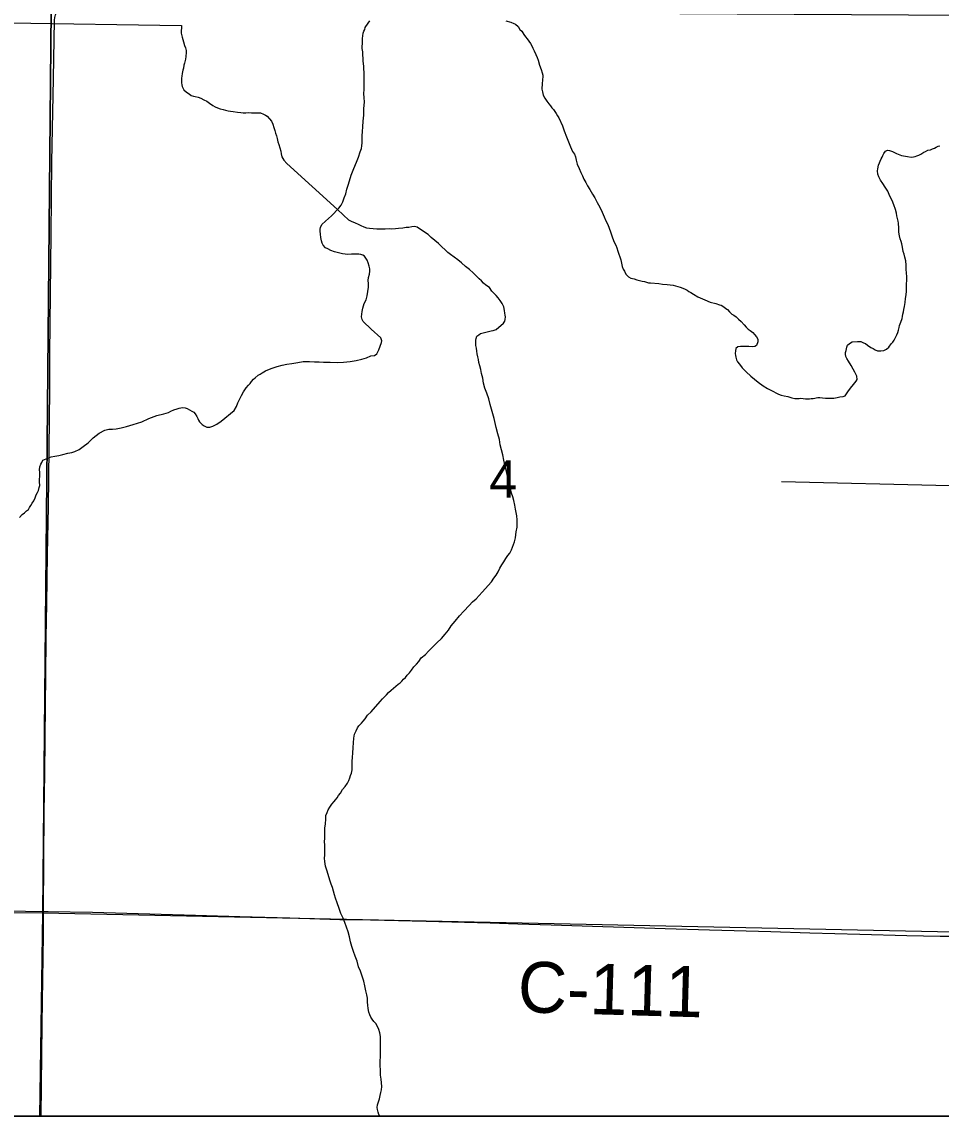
# Model space of a CAD drawing. Extents: x 2.4 to 73.1, y 4.5 to 25.6.
# Drawn here: x 31.406 to 31.92, y 17.985 to 18.597 of the extents above; entities that cross this region are included whole.
import ezdxf

# ---------------------------------------------------------------- set-up
doc = ezdxf.new("R2010")
doc.units = 0
for name, color, linetype in [('GM_X_County_Road', 7, 'Continuous'), ('GM_X_County_Road_Text', 7, 'Continuous'), ('GM_X_Interchange_Ramps', 7, 'Continuous'), ('GM_X_Minor_River', 7, 'Continuous'), ('GM_X_Section', 7, 'Continuous'), ('GM_X_Section_Text', 7, 'Continuous'), ('GM_X_Township_Road', 7, 'Continuous'), ('GM_X_US_Shield', 7, 'Continuous'), ('SH_Cut_Line', 7, 'Continuous'), ('SH_Data', 7, 'Continuous')]:
    doc.layers.add(name, color=color, linetype=linetype)

msp = doc.modelspace()

# ---------------------------------------------------------------- linework, layer by layer
at = {"layer": 'GM_X_County_Road'}
for points in [[(31.41781, 18.09961), (31.4181, 18.12841), (31.41825, 18.15482), (31.41853, 18.17658), (31.41895, 18.21542), (31.4192, 18.23096), (31.41943, 18.25271), (31.41965, 18.27135), (31.42019, 18.29932), (31.42067, 18.32573), (31.42132, 18.39098), (31.42149, 18.41118), (31.42209, 18.478), (31.42258, 18.5184), (31.42337, 18.56502), (31.42402, 18.59767), (31.42419, 18.59923), (31.42458, 18.60073), (31.42487, 18.60136), (31.42554, 18.60207)], [(30.91833, 18.10289), (30.9199, 18.10323), (30.92149, 18.1034), (30.92476, 18.10355), (30.93084, 18.10352), (30.94182, 18.10341), (30.94824, 18.10341), (30.96194, 18.1035), (30.9697, 18.1035), (30.98542, 18.10336), (31.0241, 18.10341), (31.0583, 18.10313), (31.08316, 18.10283), (31.12202, 18.10253), (31.15465, 18.1022), (31.17641, 18.10198), (31.21837, 18.10168), (31.27122, 18.10111), (31.3023, 18.1009), (31.32716, 18.10068), (31.36757, 18.10046), (31.41781, 18.09961)], [(31.41648, 17.98522), (31.41712, 18.03673), (31.41783, 18.08645), (31.41778, 18.09733), (31.41781, 18.09961)], [(31.41781, 18.09961), (31.42041, 18.09955), (31.44528, 18.09913), (31.50276, 18.09756), (31.52762, 18.0968), (31.55559, 18.09599), (31.58354, 18.09518), (31.60063, 18.09491), (31.63171, 18.09418), (31.66745, 18.09315), (31.68298, 18.09265), (31.70162, 18.09213), (31.76532, 18.09009), (31.79017, 18.08933), (31.82435, 18.08833), (31.8461, 18.08757), (31.87406, 18.08684), (31.90047, 18.08612), (31.91896, 18.08575), (31.92122, 18.08572), (31.92813, 18.08576)]]:
    msp.add_lwpolyline(points, dxfattribs=at)
at = {"layer": 'GM_X_Interchange_Ramps'}
msp.add_lwpolyline([(30.40528, 17.98522), (33.45306, 17.98522)], dxfattribs=at)
at = {"layer": 'GM_X_Minor_River'}
for points in [[(30.43533, 18.61131), (31.49498, 18.59472)], [(31.57266, 18.48187), (31.57346, 18.48356), (31.5754, 18.48541), (31.57715, 18.4869), (31.57889, 18.48838), (31.58298, 18.49265), (31.58416, 18.49434), (31.58515, 18.49621), (31.58596, 18.49847), (31.58677, 18.50054), (31.5874, 18.50319), (31.58821, 18.50545), (31.58884, 18.50791), (31.58986, 18.51111), (31.59128, 18.51488), (31.59287, 18.51826), (31.59389, 18.52109), (31.59491, 18.5241), (31.59552, 18.52599), (31.59574, 18.5275), (31.59597, 18.52921), (31.59601, 18.53092), (31.59606, 18.533), (31.59611, 18.53547), (31.59636, 18.53813), (31.59662, 18.54116), (31.59689, 18.54457), (31.59697, 18.54818), (31.59724, 18.55197), (31.5971, 18.55425), (31.59697, 18.55673), (31.59702, 18.559), (31.59708, 18.56147), (31.59714, 18.56413), (31.597, 18.56641), (31.59705, 18.5685), (31.5969, 18.5704), (31.59693, 18.57192), (31.59677, 18.57326), (31.59662, 18.57497), (31.59647, 18.57668), (31.59631, 18.57801), (31.59633, 18.57896), (31.59635, 18.57991), (31.59618, 18.58087), (31.59601, 18.58182), (31.59605, 18.58315), (31.59608, 18.58448), (31.59611, 18.586), (31.59614, 18.58752), (31.59636, 18.58884), (31.59659, 18.59035), (31.59699, 18.59149), (31.5974, 18.59243), (31.59761, 18.59356), (31.59938, 18.59599), (31.60017, 18.5973)], [(31.67621, 18.5973), (31.67904, 18.59648), (31.68074, 18.59587)], [(31.49498, 18.59472), (31.49488, 18.59036), (31.49541, 18.58826), (31.49611, 18.58559), (31.49663, 18.58349), (31.49717, 18.58214), (31.49752, 18.58081), (31.49769, 18.57966), (31.49744, 18.57739), (31.49722, 18.57588), (31.4966, 18.57361), (31.49638, 18.57247), (31.49615, 18.57077), (31.49575, 18.56983), (31.49554, 18.56889), (31.49533, 18.56794), (31.49511, 18.56643), (31.49508, 18.56529), (31.49505, 18.56396), (31.49502, 18.56263), (31.49518, 18.56149), (31.49535, 18.56053), (31.49626, 18.5588), (31.49775, 18.55744), (31.49925, 18.55646), (31.50038, 18.55567), (31.5017, 18.55526), (31.50264, 18.55505), (31.50434, 18.55463), (31.50585, 18.55403), (31.50755, 18.55323), (31.50924, 18.55243), (31.51073, 18.55126), (31.51242, 18.55008), (31.51373, 18.54929), (31.51505, 18.54869), (31.51655, 18.54809), (31.51826, 18.54767), (31.51958, 18.54745), (31.52109, 18.54704), (31.52242, 18.54682), (31.52393, 18.54659), (31.52621, 18.54635), (31.52811, 18.54612), (31.52943, 18.5459), (31.53095, 18.54587), (31.53267, 18.54602), (31.53419, 18.54598), (31.53552, 18.54595), (31.53666, 18.54593), (31.53799, 18.5459), (31.53913, 18.54587), (31.54082, 18.54507), (31.54195, 18.54467), (31.54289, 18.54408), (31.54529, 18.54117), (31.54602, 18.53964), (31.54655, 18.53773), (31.54708, 18.53601), (31.54761, 18.53447), (31.54815, 18.53313), (31.5485, 18.53161), (31.54884, 18.5297), (31.54937, 18.52817), (31.5499, 18.52626), (31.55043, 18.52453), (31.55078, 18.52301), (31.55112, 18.52129), (31.55167, 18.52033), (31.55222, 18.51937), (31.55389, 18.51762), (31.58224, 18.49187)], [(31.68074, 18.59587), (31.68168, 18.59547), (31.68317, 18.59411), (31.68408, 18.59256), (31.6852, 18.59159), (31.68575, 18.59063), (31.6863, 18.58967), (31.68722, 18.58832), (31.68814, 18.58716), (31.68907, 18.586), (31.68999, 18.58465), (31.69072, 18.5833), (31.69145, 18.58195), (31.69218, 18.58061), (31.69308, 18.5785), (31.6938, 18.57677), (31.69434, 18.57524), (31.69504, 18.57257), (31.69593, 18.57008), (31.69665, 18.56816), (31.697, 18.56701), (31.69698, 18.56587), (31.69676, 18.56474), (31.69674, 18.56379), (31.69653, 18.56265), (31.69649, 18.56114), (31.69647, 18.56019), (31.69645, 18.55905), (31.6968, 18.55771), (31.69713, 18.5558), (31.69804, 18.55407), (31.69915, 18.55234), (31.70026, 18.55099), (31.70118, 18.54982), (31.70191, 18.54867), (31.70284, 18.5477), (31.70432, 18.54558), (31.70505, 18.54423), (31.70597, 18.54307), (31.70796, 18.53866), (31.70885, 18.53579), (31.71011, 18.53253), (31.71137, 18.52965), (31.71245, 18.52697), (31.71353, 18.52429), (31.71464, 18.52274), (31.71518, 18.5214), (31.71551, 18.51949), (31.71622, 18.5172), (31.71731, 18.5147), (31.71821, 18.51259), (31.71912, 18.51067), (31.71983, 18.50876), (31.72094, 18.50702), (31.72184, 18.50511), (31.72313, 18.50299), (31.72478, 18.50048), (31.72606, 18.49836), (31.72734, 18.49586), (31.7288, 18.49317), (31.73007, 18.4903), (31.73115, 18.4878), (31.73224, 18.4855), (31.73334, 18.48357), (31.73405, 18.48147), (31.73476, 18.47936), (31.73547, 18.47707), (31.73654, 18.474), (31.73783, 18.47189), (31.73836, 18.47036), (31.73889, 18.46863), (31.73942, 18.46691), (31.73996, 18.46538), (31.74049, 18.46366), (31.74083, 18.46194), (31.74136, 18.46003), (31.7419, 18.4585), (31.74263, 18.45734), (31.74336, 18.45581), (31.74484, 18.45425), (31.74615, 18.45347), (31.74805, 18.45304), (31.74956, 18.45263), (31.75088, 18.45222), (31.75239, 18.45181), (31.75372, 18.45159), (31.75485, 18.45118), (31.75598, 18.45097), (31.75712, 18.45094), (31.76187, 18.45045), (31.76376, 18.45022), (31.76642, 18.44997), (31.76983, 18.44951), (31.77361, 18.44848), (31.77606, 18.44747), (31.77756, 18.44687), (31.7785, 18.44609), (31.77962, 18.4455), (31.78112, 18.44451), (31.78356, 18.44313), (31.78751, 18.44133)], [(31.88269, 18.41336), (31.88402, 18.41295), (31.88497, 18.41293), (31.88592, 18.41291), (31.88744, 18.41306), (31.88898, 18.41379), (31.89033, 18.4149), (31.89171, 18.41676), (31.89249, 18.4177), (31.89327, 18.41882), (31.89427, 18.4207), (31.89486, 18.42182), (31.89527, 18.42314), (31.89568, 18.42446), (31.8961, 18.42597), (31.89631, 18.42711), (31.89671, 18.42805), (31.89711, 18.42899), (31.89773, 18.43088), (31.89794, 18.43201), (31.89816, 18.43333), (31.89857, 18.43465), (31.89879, 18.43598), (31.89902, 18.43768), (31.89945, 18.43995), (31.89969, 18.44223), (31.89993, 18.44412), (31.90016, 18.4462), (31.90022, 18.44867), (31.90026, 18.45038), (31.9003, 18.45228), (31.90035, 18.45437), (31.9002, 18.45627), (31.90006, 18.45855), (31.89992, 18.46084), (31.89978, 18.46312), (31.89926, 18.46522), (31.89892, 18.46694), (31.89838, 18.46847), (31.89805, 18.47075), (31.89753, 18.47266), (31.89718, 18.474), (31.89664, 18.47553), (31.8963, 18.47725), (31.89596, 18.47916), (31.896, 18.48087), (31.89585, 18.48239), (31.89568, 18.48334), (31.8957, 18.48429), (31.89553, 18.48544), (31.89518, 18.48677), (31.89484, 18.4883), (31.89468, 18.48982), (31.89397, 18.49193), (31.89307, 18.49442), (31.89218, 18.49691), (31.89091, 18.49941), (31.88983, 18.50209), (31.88836, 18.5044), (31.88688, 18.50633), (31.88559, 18.50826), (31.88468, 18.51018), (31.88415, 18.51171), (31.884, 18.51343), (31.88421, 18.51456), (31.88464, 18.51664), (31.88605, 18.52022), (31.88664, 18.52115), (31.88704, 18.52209), (31.88745, 18.52322), (31.88843, 18.52453), (31.88958, 18.52508), (31.89072, 18.52486), (31.89242, 18.52425), (31.89467, 18.52325), (31.89731, 18.52205), (31.90071, 18.52141), (31.9028, 18.52117), (31.90414, 18.52133), (31.90509, 18.5215), (31.90605, 18.52186), (31.90701, 18.52222), (31.90816, 18.52276), (31.9099, 18.52386), (31.91085, 18.52422), (31.9122, 18.52495), (31.91354, 18.5253), (31.91469, 18.52584), (31.91584, 18.5262), (31.9168, 18.52674), (31.91796, 18.52729), (31.91876, 18.5275)], [(31.66385, 18.39491), (31.66334, 18.39759), (31.66264, 18.40026), (31.66232, 18.40255), (31.66179, 18.40446), (31.66126, 18.40637), (31.66092, 18.40809), (31.66057, 18.40961), (31.66023, 18.41114), (31.66007, 18.41266), (31.65992, 18.41438), (31.65957, 18.4159), (31.65942, 18.41743), (31.65945, 18.41876), (31.65966, 18.4197), (31.66007, 18.42102), (31.66123, 18.42176), (31.66219, 18.42249), (31.66354, 18.42303), (31.66507, 18.42338), (31.66659, 18.42372), (31.66812, 18.42407), (31.66927, 18.42423), (31.6708, 18.42477), (31.67235, 18.42606), (31.67351, 18.42699), (31.67487, 18.42829), (31.67566, 18.42941), (31.67587, 18.43035), (31.67609, 18.43187), (31.67592, 18.43282), (31.67576, 18.43397), (31.6756, 18.43549), (31.67508, 18.4374), (31.67417, 18.43932), (31.67307, 18.44105), (31.67196, 18.4426), (31.67085, 18.44376), (31.66973, 18.44493), (31.66843, 18.44629), (31.66715, 18.44821), (31.66508, 18.44959), (31.66378, 18.45076), (31.66267, 18.45192), (31.66136, 18.45309), (31.65988, 18.45465), (31.65801, 18.4564), (31.65597, 18.45834), (31.65373, 18.4601), (31.65149, 18.46205), (31.64944, 18.46381), (31.64738, 18.46518), (31.64532, 18.46675), (31.64383, 18.46792), (31.64234, 18.46928), (31.64047, 18.47104), (31.63861, 18.47279), (31.63656, 18.47454), (31.63451, 18.4763), (31.63283, 18.47786), (31.62796, 18.481), (31.62665, 18.48198), (31.62533, 18.48239), (31.62381, 18.48224), (31.62209, 18.4819), (31.62057, 18.48174), (31.61866, 18.4814), (31.61637, 18.48127), (31.61466, 18.48111), (31.61256, 18.48097), (31.61104, 18.481), (31.60876, 18.48087), (31.60648, 18.48092), (31.6042, 18.48097), (31.60211, 18.48102), (31.60002, 18.48125), (31.59851, 18.48148), (31.597, 18.48208), (31.59549, 18.48268), (31.59399, 18.48348), (31.5923, 18.48428), (31.59003, 18.48509), (31.58853, 18.48588), (31.58223, 18.49186)], [(31.5019, 18.37861), (31.50264, 18.37765), (31.50356, 18.37611), (31.5041, 18.37515), (31.50446, 18.37419), (31.50501, 18.37323), (31.5065, 18.37167), (31.50762, 18.37089), (31.50913, 18.37028), (31.51084, 18.37025), (31.51256, 18.37078), (31.51468, 18.37187), (31.51719, 18.37352), (31.52436, 18.37963), (31.52573, 18.38169), (31.52654, 18.38376), (31.52754, 18.38601), (31.52853, 18.38789), (31.52972, 18.38995), (31.5311, 18.3922), (31.53247, 18.39369), (31.53344, 18.39462), (31.53403, 18.39575), (31.53521, 18.39705), (31.53617, 18.39779), (31.53792, 18.39927), (31.53888, 18.39981), (31.54004, 18.40055), (31.54196, 18.40165), (31.54504, 18.4031), (31.54848, 18.40416), (31.55135, 18.40485), (31.55383, 18.40537), (31.55669, 18.40587), (31.55994, 18.40637), (31.56299, 18.40687), (31.5666, 18.40698), (31.56926, 18.40673), (31.57192, 18.40667), (31.57439, 18.40661), (31.578, 18.40653), (31.58199, 18.40644), (31.5856, 18.40655), (31.58922, 18.40685), (31.59266, 18.40753), (31.59572, 18.40822), (31.59839, 18.40892), (31.60089, 18.41001), (31.6028, 18.41034), (31.60415, 18.41126), (31.60534, 18.41352), (31.60596, 18.41559), (31.60676, 18.41747), (31.60697, 18.41842), (31.60644, 18.42014), (31.60458, 18.42189), (31.6029, 18.42326), (31.60104, 18.42501), (31.59657, 18.42929), (31.59603, 18.43044), (31.59568, 18.43197), (31.59571, 18.43329), (31.59594, 18.43481), (31.59636, 18.4367), (31.59718, 18.43934), (31.59818, 18.44141), (31.5988, 18.44367), (31.59923, 18.44613), (31.59947, 18.44841), (31.59952, 18.45049), (31.59937, 18.45221), (31.5996, 18.45391), (31.60002, 18.4558), (31.60025, 18.4575), (31.60027, 18.45864), (31.59993, 18.46017), (31.5994, 18.46208), (31.59868, 18.46362), (31.59794, 18.46477), (31.5972, 18.46574), (31.59626, 18.46633), (31.59532, 18.46673), (31.59419, 18.46695), (31.5921, 18.467), (31.59, 18.46685), (31.58791, 18.46671), (31.58639, 18.46693), (31.58507, 18.46715), (31.5828, 18.46759), (31.58053, 18.46821), (31.57846, 18.46901), (31.57676, 18.46981), (31.57545, 18.47041), (31.57415, 18.47196), (31.57361, 18.47311), (31.57326, 18.47445), (31.57291, 18.47616), (31.57277, 18.47807), (31.57243, 18.47978), (31.57245, 18.48092), (31.57266, 18.48187)], [(31.78751, 18.44133), (31.79053, 18.44012), (31.79355, 18.43929), (31.79563, 18.43868), (31.79657, 18.43847), (31.79807, 18.43748), (31.79919, 18.43651), (31.80013, 18.43592), (31.80124, 18.43475), (31.80254, 18.43339), (31.80367, 18.4328), (31.80498, 18.43182), (31.80628, 18.43065), (31.80777, 18.42929), (31.80944, 18.42735), (31.81055, 18.42619), (31.81167, 18.42502), (31.81279, 18.42424), (31.81429, 18.42306), (31.81522, 18.42209), (31.81633, 18.42074), (31.81706, 18.41939), (31.81702, 18.41787), (31.81641, 18.4158), (31.81544, 18.41525), (31.81411, 18.41509), (31.81202, 18.41533), (31.80974, 18.41538), (31.80746, 18.41524), (31.80593, 18.41508), (31.80477, 18.41416), (31.80455, 18.41284), (31.80452, 18.41132), (31.80469, 18.41036), (31.80485, 18.40941), (31.8052, 18.40788), (31.80575, 18.40673), (31.80686, 18.40538), (31.80833, 18.40344), (31.81056, 18.40111), (31.81317, 18.39878), (31.81728, 18.39545), (31.82008, 18.3933), (31.82252, 18.39192), (31.8244, 18.39093), (31.8259, 18.39013), (31.82722, 18.38934), (31.82872, 18.38874), (31.83023, 18.38814), (31.83174, 18.38772), (31.83382, 18.3873), (31.83609, 18.38668), (31.83779, 18.38626), (31.83893, 18.38623), (31.84026, 18.3862), (31.84122, 18.38637), (31.84236, 18.38634), (31.84368, 18.38613), (31.84501, 18.38609), (31.84596, 18.38607), (31.84692, 18.38624), (31.84806, 18.38622), (31.85073, 18.38673), (31.85168, 18.38689), (31.8532, 18.38667), (31.8549, 18.38644), (31.85604, 18.38642), (31.85757, 18.38638), (31.85966, 18.38653), (31.86138, 18.38687), (31.86291, 18.38721), (31.86481, 18.38736), (31.86596, 18.38771), (31.86734, 18.38996), (31.86891, 18.39202), (31.87066, 18.39407), (31.87204, 18.39593), (31.87263, 18.39687), (31.87248, 18.39877), (31.87139, 18.40089), (31.87048, 18.40262), (31.86919, 18.40473), (31.86772, 18.40705), (31.86681, 18.40859), (31.86626, 18.40974), (31.8661, 18.41107), (31.86613, 18.41202), (31.86653, 18.41315), (31.86676, 18.41486), (31.86717, 18.41599), (31.86833, 18.41691), (31.86987, 18.41783), (31.87273, 18.41814), (31.87368, 18.41812), (31.87463, 18.4181), (31.87613, 18.4173), (31.87726, 18.4169), (31.87838, 18.41611), (31.88025, 18.41474), (31.88157, 18.41414), (31.88269, 18.41336)], [(31.58912, 18.17418), (31.58953, 18.1755), (31.58994, 18.17682), (31.59037, 18.17871), (31.59042, 18.18099), (31.59047, 18.18345), (31.59052, 18.18573), (31.59076, 18.18801), (31.59103, 18.19123), (31.59109, 18.19389), (31.59133, 18.19635), (31.59176, 18.19862), (31.59257, 18.2005), (31.59336, 18.20219), (31.59415, 18.20331), (31.59551, 18.2048), (31.59649, 18.20592), (31.59766, 18.20722), (31.59904, 18.20928), (31.60098, 18.21114), (31.60605, 18.21691), (31.60742, 18.2184), (31.60859, 18.2197), (31.60956, 18.22063), (31.61073, 18.22194), (31.61209, 18.22323), (31.61344, 18.22434), (31.6148, 18.22545), (31.61615, 18.22656), (31.61712, 18.2273), (31.61809, 18.22823), (31.61907, 18.22935), (31.62023, 18.23027), (31.62121, 18.23158), (31.62238, 18.23288), (31.62355, 18.23437), (31.62493, 18.23624), (31.62629, 18.23773), (31.62765, 18.23922), (31.62903, 18.24128), (31.63135, 18.24313), (31.63311, 18.24499), (31.63525, 18.24722), (31.63777, 18.24963), (31.6403, 18.25204), (31.64244, 18.25446), (31.64421, 18.2567), (31.64578, 18.25914), (31.64793, 18.26175), (31.65028, 18.26473), (31.65281, 18.26734), (31.65573, 18.2705), (31.65768, 18.27254), (31.65962, 18.27421), (31.66137, 18.27607), (31.66312, 18.27793), (31.66488, 18.27998), (31.66644, 18.28184), (31.6682, 18.28389), (31.66957, 18.28576), (31.67094, 18.28744), (31.67193, 18.28932), (31.67293, 18.29138), (31.67411, 18.29326), (31.6751, 18.29494), (31.67628, 18.29682), (31.67746, 18.2985), (31.67844, 18.29981), (31.67944, 18.30168), (31.68106, 18.30621), (31.68168, 18.30847), (31.68213, 18.31169), (31.68257, 18.31434), (31.68262, 18.31643), (31.68267, 18.31852), (31.68233, 18.32061), (31.682, 18.32252), (31.68166, 18.32443), (31.68133, 18.32671), (31.68082, 18.3292), (31.6801, 18.3313), (31.67939, 18.33341), (31.6787, 18.33665), (31.67781, 18.33933), (31.67731, 18.34219), (31.67662, 18.34543), (31.67593, 18.34849), (31.67524, 18.35173), (31.67455, 18.35479), (31.67385, 18.35765), (31.67315, 18.36033), (31.67265, 18.36338), (31.67177, 18.36644), (31.6709, 18.37006), (31.66968, 18.37503), (31.66863, 18.37904), (31.66758, 18.38287), (31.6667, 18.38611), (31.66563, 18.38918), (31.66455, 18.39205), (31.66385, 18.39491)], [(31.40439, 18.31984), (31.40595, 18.32151), (31.4073, 18.32243), (31.40846, 18.32354), (31.40943, 18.32428), (31.41003, 18.32541), (31.41081, 18.32653), (31.4116, 18.32784), (31.41239, 18.32915), (31.41319, 18.33066), (31.4138, 18.33235), (31.41459, 18.33366), (31.41499, 18.33479), (31.41541, 18.33649), (31.41582, 18.33762), (31.41567, 18.33972), (31.41571, 18.34143), (31.41574, 18.34256), (31.41576, 18.34351), (31.41579, 18.34503), (31.41563, 18.34637), (31.41586, 18.34807), (31.41646, 18.34958), (31.41687, 18.35052), (31.41747, 18.35183), (31.42207, 18.35363), (31.42417, 18.35396), (31.42646, 18.35448), (31.42875, 18.355), (31.43143, 18.3557), (31.43372, 18.35603), (31.43544, 18.35656), (31.43775, 18.35783), (31.44007, 18.35949), (31.44278, 18.36152), (31.44569, 18.3643), (31.44898, 18.36689), (31.45206, 18.36853), (31.45435, 18.36905), (31.45645, 18.36919), (31.45854, 18.36933), (31.46121, 18.36984), (31.46427, 18.37053), (31.46791, 18.37178), (31.47289, 18.37319), (31.47673, 18.375), (31.48114, 18.3768), (31.48515, 18.37766), (31.48764, 18.37836), (31.48899, 18.37909), (31.49072, 18.38), (31.49263, 18.38053), (31.49378, 18.38089), (31.4955, 18.38123), (31.49701, 18.381), (31.49815, 18.3806), (31.49946, 18.38), (31.50078, 18.37921), (31.5019, 18.37861)], [(31.60583, 17.98522), (31.60524, 17.98616), (31.60489, 17.98749), (31.60454, 17.98883), (31.60437, 17.98997), (31.6046, 17.99149), (31.60501, 17.99319), (31.60562, 17.99488), (31.60605, 17.99677), (31.60646, 17.99847), (31.60669, 17.99999), (31.60692, 18.00169), (31.60663, 18.00588), (31.6063, 18.00816), (31.60617, 18.01083), (31.60604, 18.01349), (31.6061, 18.01615), (31.60615, 18.01842), (31.6062, 18.0207), (31.60625, 18.02298), (31.60631, 18.02564), (31.60617, 18.02773), (31.60621, 18.02963), (31.60588, 18.03173), (31.60535, 18.03364), (31.60463, 18.03536), (31.60353, 18.03691), (31.60241, 18.03807), (31.60149, 18.03942), (31.60076, 18.04058), (31.60021, 18.04173), (31.59968, 18.04326), (31.59934, 18.04536), (31.5992, 18.04726), (31.59904, 18.04897), (31.5989, 18.05107), (31.59856, 18.05297), (31.59805, 18.05527), (31.59753, 18.05794), (31.59683, 18.06061), (31.59595, 18.06348), (31.59506, 18.06616), (31.59397, 18.06865), (31.5931, 18.0719), (31.59202, 18.07458), (31.59113, 18.07726), (31.59024, 18.07994), (31.58953, 18.08262), (31.58884, 18.08548), (31.58814, 18.08816), (31.58725, 18.09084), (31.58635, 18.09333), (31.58527, 18.09582), (31.584, 18.09851), (31.58311, 18.10119), (31.58204, 18.10444), (31.58115, 18.10693), (31.58043, 18.10884), (31.57991, 18.11095), (31.57938, 18.11305), (31.57866, 18.11477), (31.57813, 18.11649), (31.57618, 18.12262), (31.57547, 18.12491), (31.57515, 18.12758), (31.575, 18.12929), (31.57503, 18.131), (31.57507, 18.13271), (31.57512, 18.13461), (31.57516, 18.13669), (31.57501, 18.1386), (31.57505, 18.1403), (31.5751, 18.1422), (31.57514, 18.1441), (31.57519, 18.14638), (31.57543, 18.14846), (31.57568, 18.15131), (31.57572, 18.1532), (31.57633, 18.1549), (31.57694, 18.15641), (31.57792, 18.1579), (31.5791, 18.15959), (31.58027, 18.16108), (31.58105, 18.16201), (31.58203, 18.16313), (31.58282, 18.16444), (31.5838, 18.16575), (31.58499, 18.16781), (31.58655, 18.16949), (31.58773, 18.17136), (31.58852, 18.17286), (31.58912, 18.17418)]]:
    msp.add_lwpolyline(points, dxfattribs=at)
at = {"layer": 'GM_X_Section'}
for points in [[(30.9167, 18.60894), (30.95137, 18.60852), (31.42217, 18.60344), (31.41744, 18.09871), (30.91045, 18.10349)], [(31.42217, 18.60344), (31.45381, 18.60328), (31.93338, 18.60046), (31.92638, 18.08802), (31.41744, 18.09871)]]:
    msp.add_lwpolyline(points, close=True, dxfattribs=at)
at = {"layer": 'GM_X_Township_Road'}
msp.add_lwpolyline([(31.83037, 18.33979), (31.92435, 18.33759), (31.93148, 18.33749)], dxfattribs=at)
at = {"layer": 'GM_X_US_Shield'}
for points in [[(30.90891, 17.98522), (31.41579, 17.98522), (31.41744, 18.09871), (30.91045, 18.10349)], [(31.41579, 17.98522), (31.92492, 17.98522), (31.92638, 18.08802), (31.41744, 18.09871)]]:
    msp.add_lwpolyline(points, close=True, dxfattribs=at)
at = {"layer": 'SH_Cut_Line'}
msp.add_lwpolyline([(29.49738, 21.67933), (29.49738, 17.98522), (36.29738, 17.98522), (36.29738, 20.02567)], dxfattribs=at)
at = {"layer": 'SH_Data'}
msp.add_lwpolyline([(29.49738, 24.78522), (36.29738, 24.78522), (36.29738, 17.98522), (29.49738, 17.98522)], close=True, dxfattribs=at)

# ---------------------------------------------------------------- texts
at = {"layer": 'GM_X_County_Road_Text'}
msp.add_text('C-111', height=0.028409, rotation=358.34755, dxfattribs=at).set_placement((31.68268, 18.04337))
at = {"layer": 'GM_X_Section_Text'}
msp.add_text('4', height=0.02093, rotation=0.00001, dxfattribs=at).set_placement((31.66702, 18.33081))

doc.saveas('drawing.dxf')
